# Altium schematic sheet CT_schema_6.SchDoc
size 384 x 301 mm
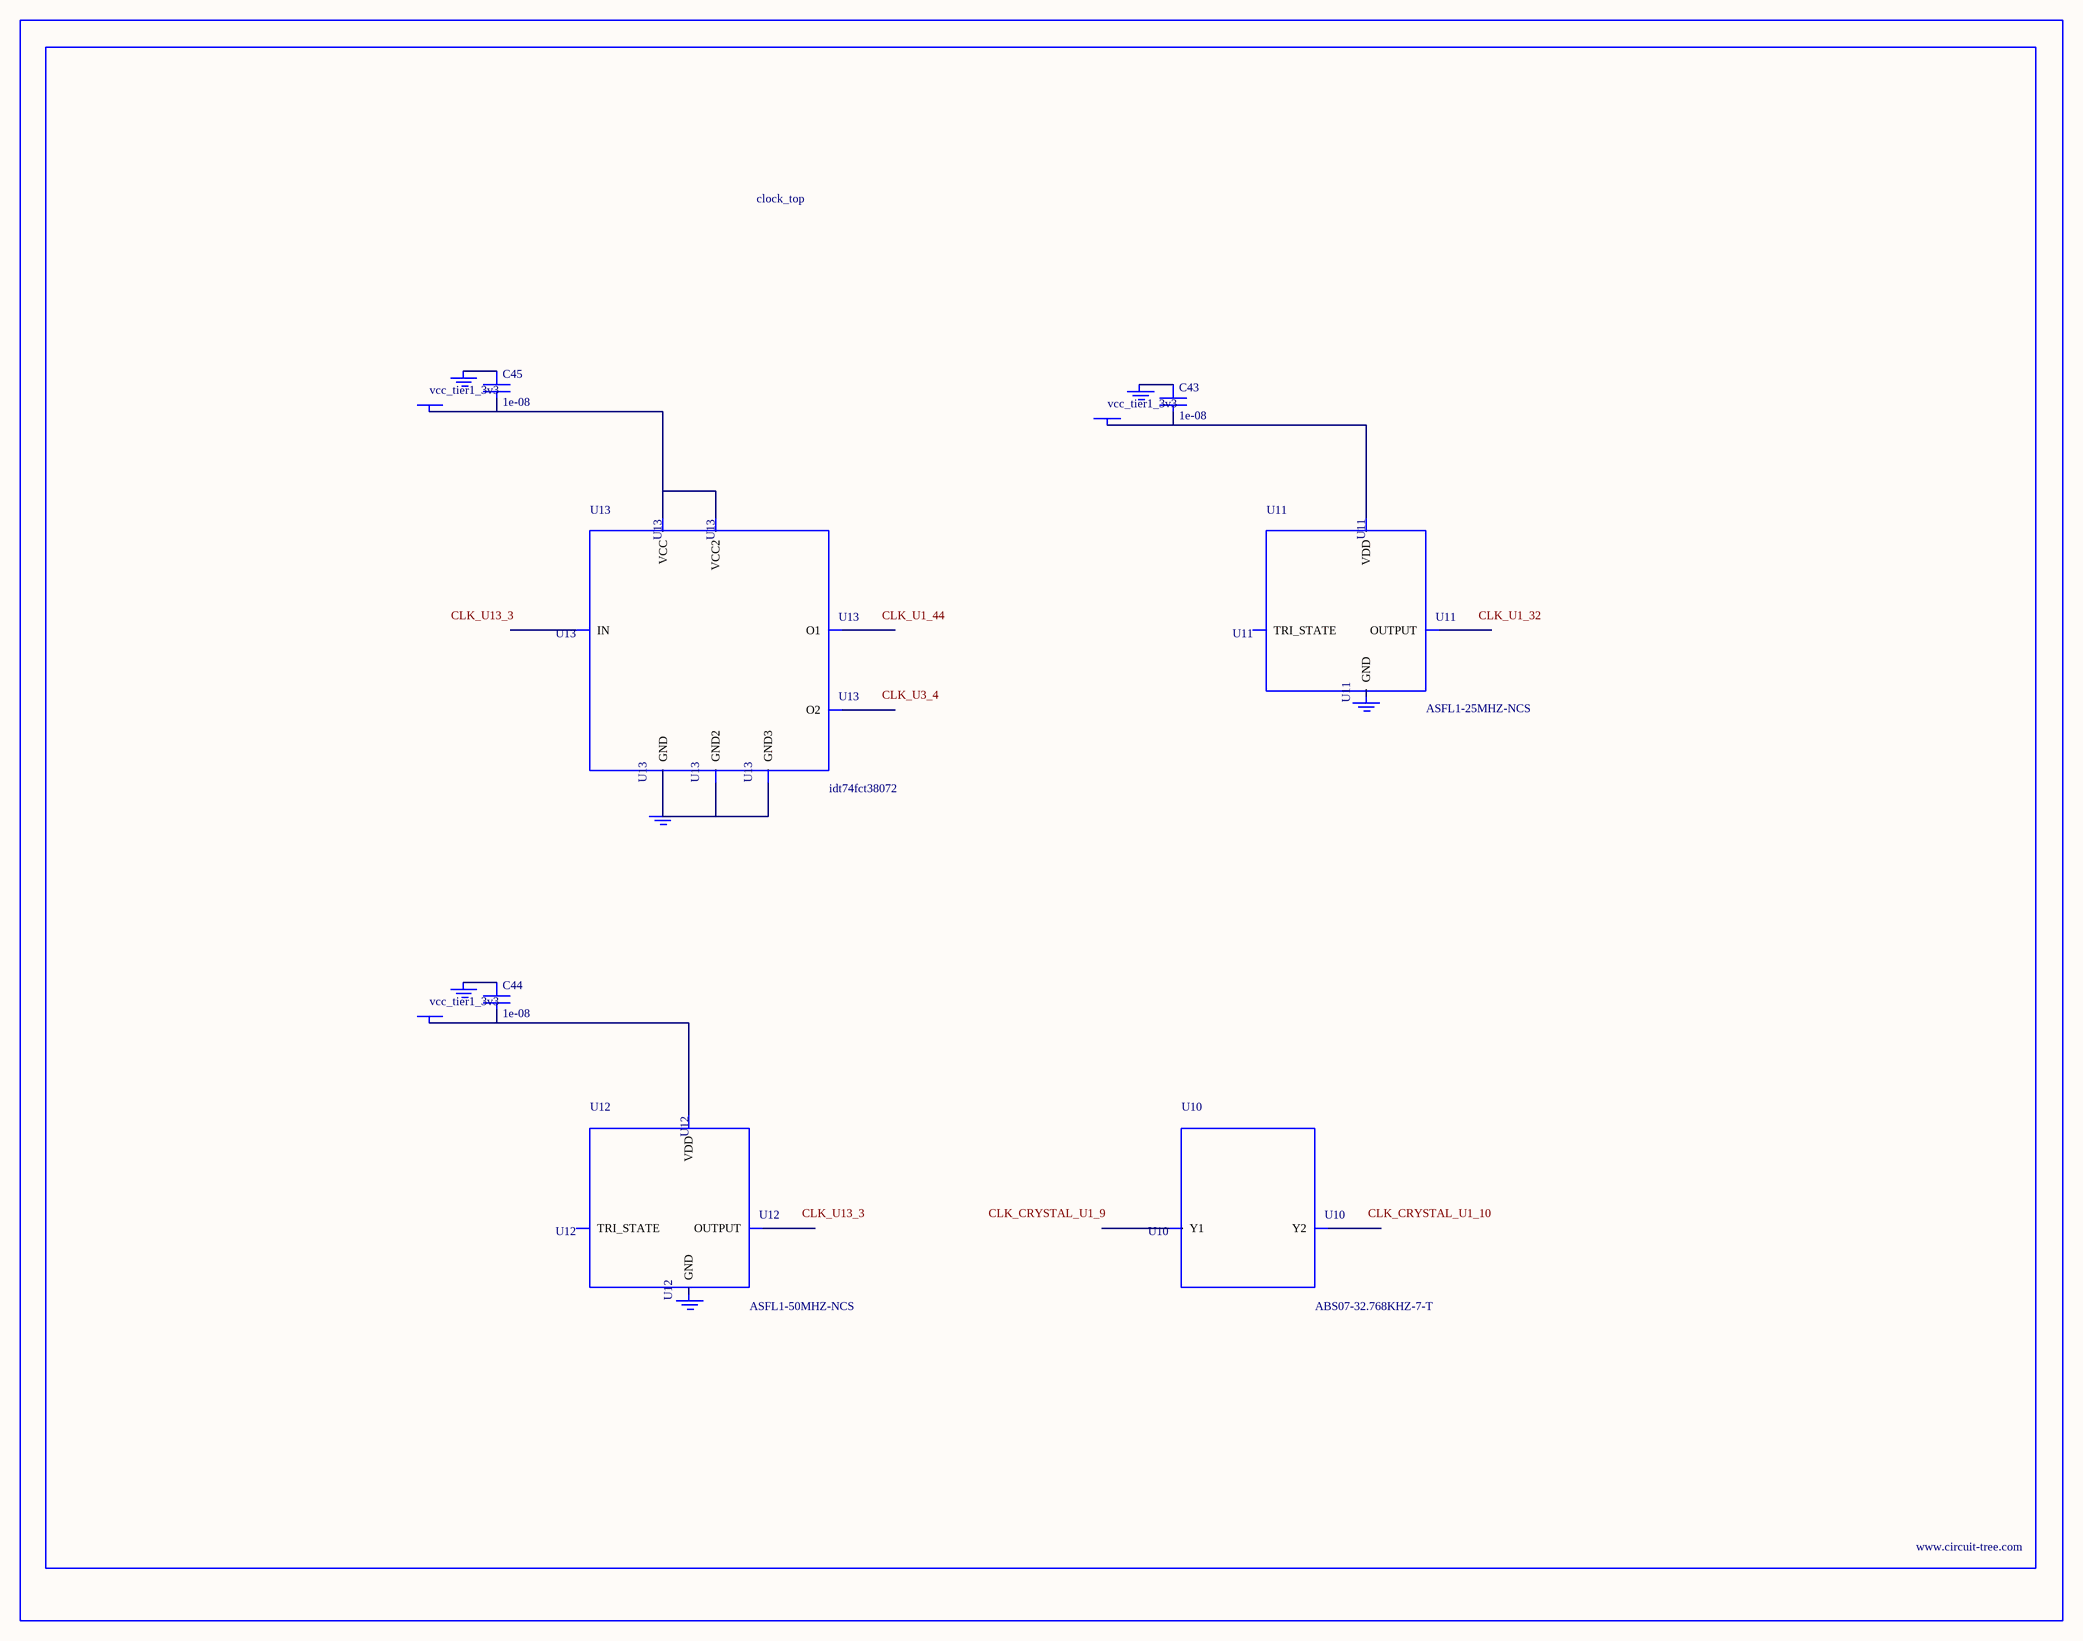
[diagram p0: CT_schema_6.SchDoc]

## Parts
BORDER5  (no value)
C43  1e-08  [C0402]
C44  1e-08  [C0402]
C45  1e-08  [C0402]
GND_INSTANCE_5_0  (no value)
GND_INSTANCE_5_1  (no value)
GND_INSTANCE_5_2  (no value)
GND_INSTANCE_5_3  (no value)
GND_INSTANCE_5_4  (no value)
GND_INSTANCE_5_5  (no value)
POWER_INSTANCE_5_0  vcc_tier1_3v3
POWER_INSTANCE_5_1  vcc_tier1_3v3
POWER_INSTANCE_5_2  vcc_tier1_3v3
U10  ABS07-32.768KHZ-7-T  [ABS07-32.768KHZ-7-T]
U11  ASFL1-25MHZ-NCS  [ASFL1]
U12  ASFL1-50MHZ-NCS  [ASFL1]
U13  idt74fct38072  [IDT74FCT38072]

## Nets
NetC43_1: C43.1 GND_INSTANCE_5_0.0(GND)
NetC43_2: C43.2 POWER_INSTANCE_5_0.0(PWR) U11.4(VDD)
NetC44_1: C44.1 GND_INSTANCE_5_2.0(GND)
NetC44_2: C44.2 POWER_INSTANCE_5_1.0(PWR) U12.4(VDD)
NetC45_1: C45.1 GND_INSTANCE_5_4.0(GND)
NetC45_2: C45.2 POWER_INSTANCE_5_2.0(PWR) U13.1(VCC) U13.2(VCC2)
NetGND_INSTANCE_5_5_0: GND_INSTANCE_5_5.0(GND) U13.4(GND) U13.5(GND2) U13.8(GND3)

Not connected (* = marked no-connect by the designer): GND_INSTANCE_5_1 0(GND); GND_INSTANCE_5_3 0(GND); U10 1(Y1) 2(Y2); U11 1(TRI_STATE) 2(GND) 3(OUTPUT); U12 1(TRI_STATE) 2(GND) 3(OUTPUT); U13 3(IN) 6(O2) 7(O1)

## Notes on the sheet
- Labels drawn without touching a wire or pin: CLK_CRYSTAL_U1_9, CLK_CRYSTAL_U1_10, CLK_U1_32, CLK_U1_44, CLK_U3_4, CLK_U13_3

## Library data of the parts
BORDER5 = BORDER_PAGE5
C43-C45 = C0402C103K3RAC
GND_INSTANCE_5_0-GND_INSTANCE_5_5 = GND
POWER_INSTANCE_5_0-POWER_INSTANCE_5_2 = PWR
